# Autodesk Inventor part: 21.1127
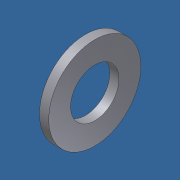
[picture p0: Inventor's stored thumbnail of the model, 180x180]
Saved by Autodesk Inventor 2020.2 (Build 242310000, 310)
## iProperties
Created: 2006-02
Part Number: 21.1127
Material: Steel, Mild
Description: M8 ROUND WASHER
Document SubType Name: Modeling
Standard: DIN 125
Designer: Andy Moles
Standards Organization: DIN
Language: en-US
Size Designation: A 8.4
Categories: <MemberInstance><Categories><Category DisplayName="Fasteners" InternalName="e4da775c-781d-43d5-af7c-5136215cf5a6" Mnemonic="FSTN"><Category DisplayName="Washers
Mass: 1.82929 g
Surface Area: 4.13936 cm^2
Volume: 0.233031 cm^3
Density: 7.85 g/cm^3
Vendor: S
Appearance: Zinc
Author: Andy Moles
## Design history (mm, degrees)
sketch "Sketch"
  geometry: C1 r 8 at (0, 0); C2 r 4.2 at (0, 0); 1 further point
  constraints: 2 centre point, 2 coincident
  dimensions: "d0" = 8.4 diameter of C2 (= SD1); "d1" = 16 diameter of C1 (= SD2)
extrude "Body" new body sketch "Sketch" distance "d2" = 1.6 (= SD); taper "d3" = 0 deg
workaxis "Work Axis1"
workplane "Work Plane1"
body "Solid1"
other parameters: "SD1" = 8.4 [user parameter; used in 1 equation term], "SD2" = 16 [user parameter; used in 1 equation term], "SD" = 1.6 [user parameter; used in 1 equation term], "d4" = 0, "d5" = 0, "d6" = 0, "d7" = 0, "NND" = 8 [user parameter]
